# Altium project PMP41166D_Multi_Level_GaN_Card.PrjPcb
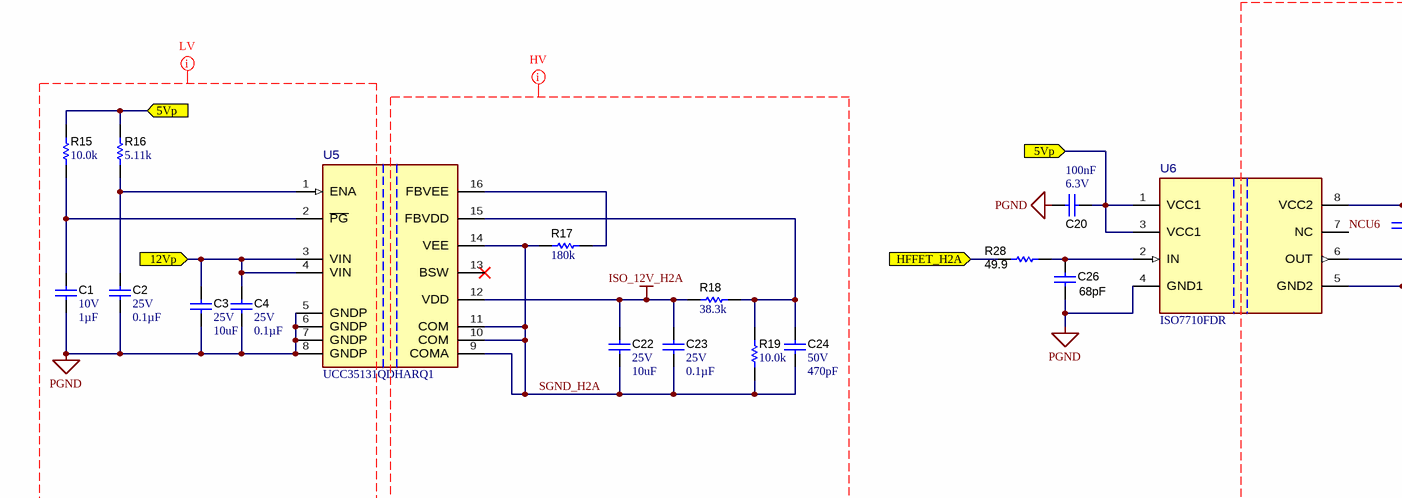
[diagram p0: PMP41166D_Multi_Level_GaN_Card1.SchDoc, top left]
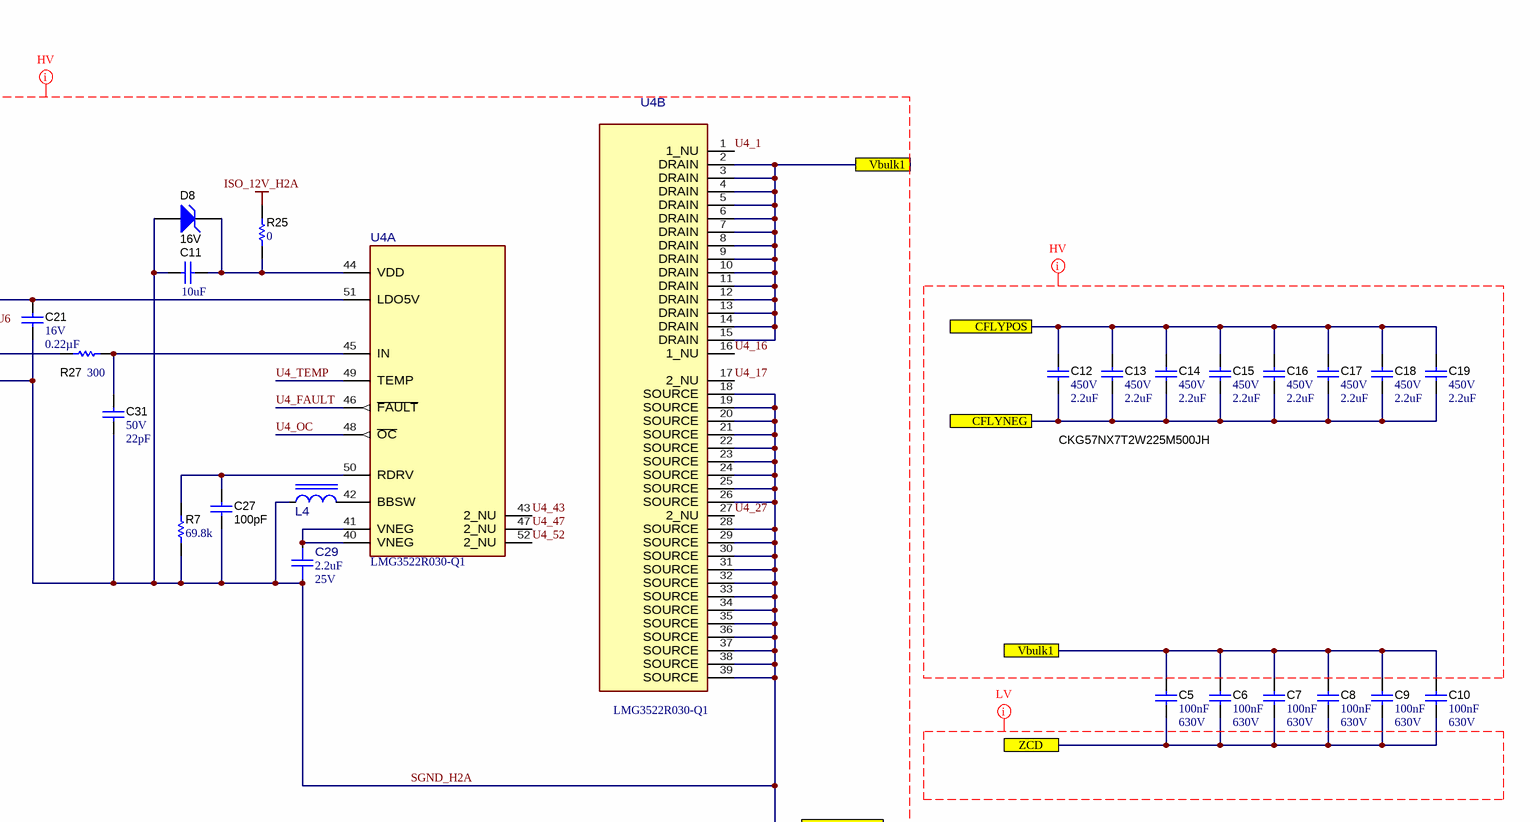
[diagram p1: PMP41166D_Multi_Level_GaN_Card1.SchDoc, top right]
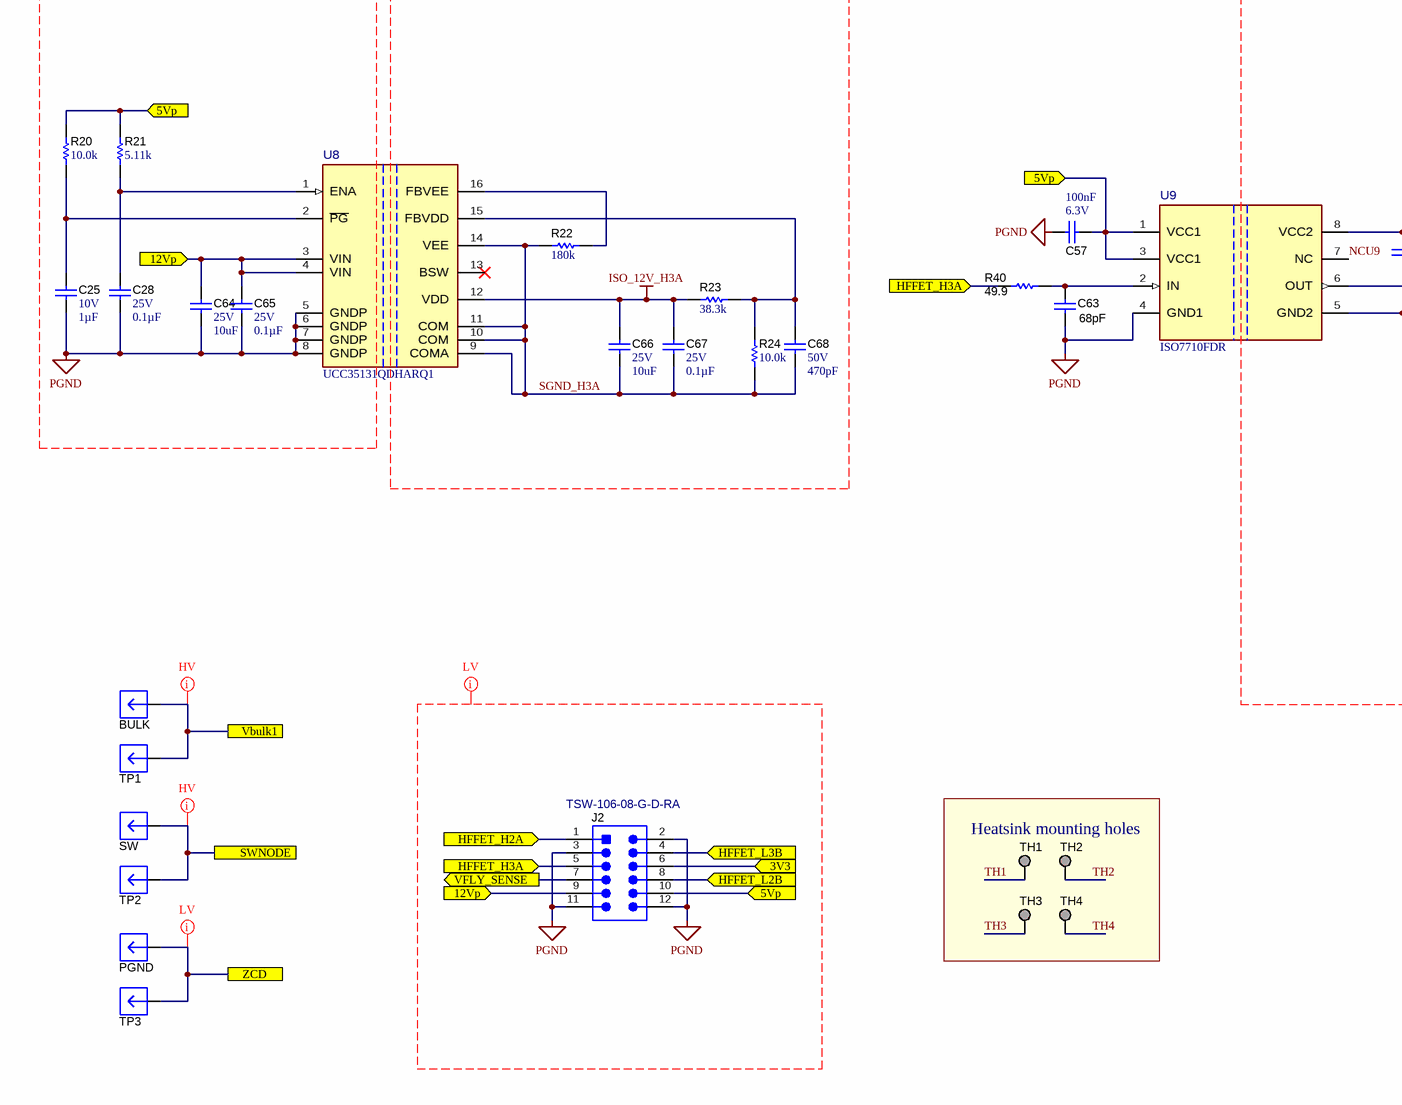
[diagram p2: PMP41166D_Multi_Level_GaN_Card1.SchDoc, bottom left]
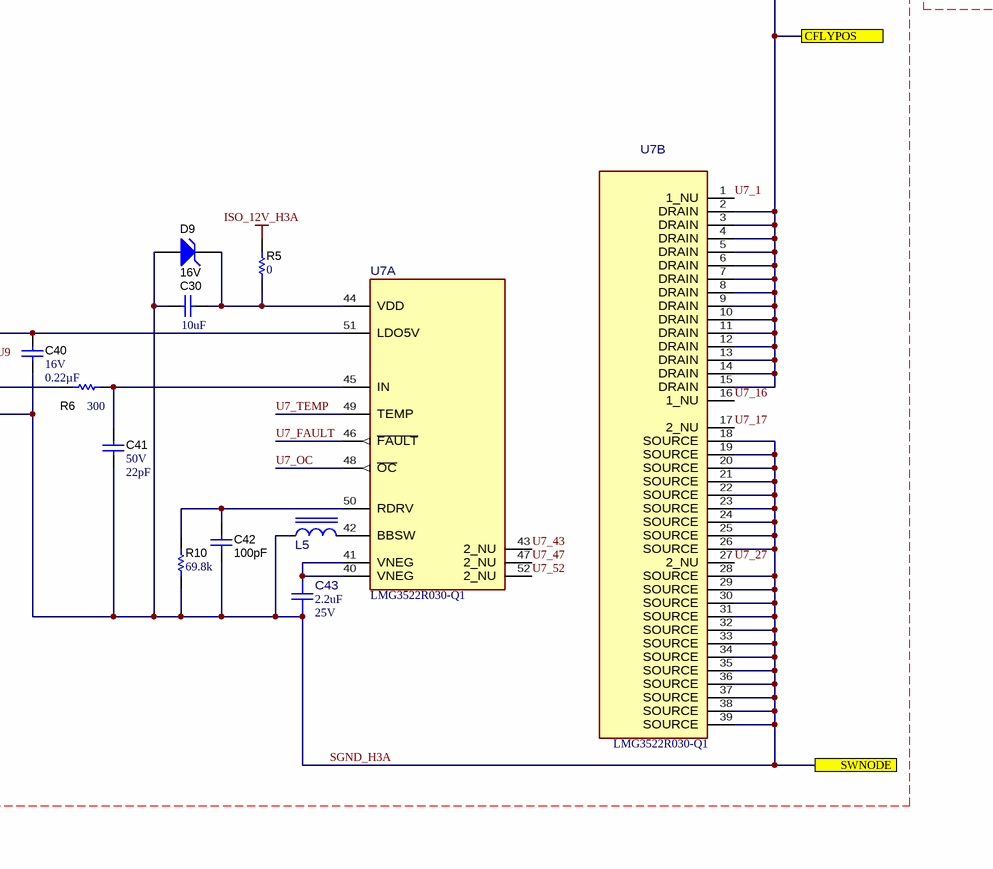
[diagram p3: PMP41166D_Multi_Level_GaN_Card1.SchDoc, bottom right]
CopyrightYear: 2025; PCB_Layout: B. Sun / E. Chen; PCB_Rev: D; PRJ_Customer: Public Release; PRJ_Engineer: B. Sun / E. Chen; PRJ_Number: PMP41166_GaN; PRJ_Title: PMP41166 GaN Card; SCH_Rev: D; TechSupport: http://www.ti.com/support; TID: N/A
3 sheets, 178 parts. Net scope: flat (ports and power ports of the same name join across sheets).
Board file: PMP41166D_Multi_Level_GaN_Card.PcbDoc
Sheets:
  PMP41166D_Multi_Level_GaN_Card1.SchDoc
  PMP41166D_Multi_Level_GaN_Card2.SchDoc
  PMP41166D_Multi_Level_GaN_Card_Hardware.SchDoc

## Sheet PMP41166D_Multi_Level_GaN_Card1.SchDoc
size A2; Date: Not shown in title block; ApprovedBy: Not shown in title block; CheckedBy: Not shown in title block; Author: Not shown in title block; CompanyName: Not shown in title block; Engineer: Not shown in title block; Organization: Not shown in title block; Address1: Not shown in title block; Address2: Not shown in title block; Address3: Not shown in title block; Address4: Not shown in title block; DocumentNumber: 1; Revision: Use project parameter SCH_Rev; SheetNumber: 1; SheetTotal: 3; PageSetup: Record=PageOptions¦CenterHorizontal=True¦CenterVertical=True¦PrintScale=0.69¦XCorrection=1.00¦YCorrection=1.00¦PrintKind=0¦BorderSize=5000000¦LeftOffset=0¦BottomOffset=0¦Orientation=2¦PaperLength=1000¦PaperWidth=1000¦Scale=100¦PaperSource=15¦PrintQuality=600¦MediaType=1¦DitherType=10¦PaperKind=Letter¦PrintScaleMode=1

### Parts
BULK  3621-0-32-15-00-00-08-0  [Mill-Max_3621-0-32-xx-00-00-08-0]  (value not drawn)
C1  VDC_V: 10V  ValueDisplayed: 1µF  [0402]  (hidden comment: CC0402MRX5R6BB105)
C2  VDC_V: 25V  ValueDisplayed: 0.1µF  [0402]  (hidden comment: CGA2B3X7R1E104K050BB)
C3  VDC_V: 25V  ValueDisplayed: 10uF  [0603]  (hidden comment: C1608X5R1E106M080AC)
C4  VDC_V: 25V  ValueDisplayed: 0.1µF  [0402]  (hidden comment: CGA2B3X7R1E104K050BB)
C5  Cap_F: 100nF  VDC_V: 630V  [1210]  (hidden comment: C3225X7T2J104K160AC)
C6  Cap_F: 100nF  VDC_V: 630V  [1210]  (hidden comment: C3225X7T2J104K160AC)
C7  Cap_F: 100nF  VDC_V: 630V  [1210]  (hidden comment: C3225X7T2J104K160AC)
C8  Cap_F: 100nF  VDC_V: 630V  [1210]  (hidden comment: C3225X7T2J104K160AC)
C9  Cap_F: 100nF  VDC_V: 630V  [1210]  (hidden comment: C3225X7T2J104K160AC)
C10  Cap_F: 100nF  VDC_V: 630V  [1210]  (hidden comment: C3225X7T2J104K160AC)
C11  ValueDisplayed: 10uF  [0603]  (hidden comment: GRM188R61E106MA73D)
C12  CKG57NX7T2W225M500JH  VDC_V: 450V  ValueDisplayed: 2.2uF  [CKG57N]
C13  VDC_V: 450V  ValueDisplayed: 2.2uF  [CKG57N]  (hidden comment: CKG57NX7T2W225M500JH)
C14  VDC_V: 450V  ValueDisplayed: 2.2uF  [CKG57N]  (hidden comment: CKG57NX7T2W225M500JH)
C15  VDC_V: 450V  ValueDisplayed: 2.2uF  [CKG57N]  (hidden comment: CKG57NX7T2W225M500JH)
C16  VDC_V: 450V  ValueDisplayed: 2.2uF  [CKG57N]  (hidden comment: CKG57NX7T2W225M500JH)
C17  VDC_V: 450V  ValueDisplayed: 2.2uF  [CKG57N]  (hidden comment: CKG57NX7T2W225M500JH)
C18  VDC_V: 450V  ValueDisplayed: 2.2uF  [CKG57N]  (hidden comment: CKG57NX7T2W225M500JH)
C19  VDC_V: 450V  ValueDisplayed: 2.2uF  [CKG57N]  (hidden comment: CKG57NX7T2W225M500JH)
C20  Cap_F: 100nF  VDC_V: 6.3V  [0603]  (hidden comment: GRM188R70J104KA01D)
C21  VDC_V: 16V  ValueDisplayed: 0.22µF  [0402]  (hidden comment: GCM155R71C224KE02D)
C22  VDC_V: 25V  ValueDisplayed: 10uF  [0603]  (hidden comment: C1608X5R1E106M080AC)
C23  VDC_V: 25V  ValueDisplayed: 0.1µF  [0402]  (hidden comment: CGA2B3X7R1E104K050BB)
C24  VDC_V: 50V  ValueDisplayed: 470pF  [0402]  (hidden comment: GRM155R71H471KA01D)
C25  VDC_V: 10V  ValueDisplayed: 1µF  [0402]  (hidden comment: CC0402MRX5R6BB105)
C26  ValueDisplayed: 68pF  [0402]  (hidden comment: C1005C0G1H680J050BA)
C27  ValueDisplayed: 100pF  [0402]  (hidden comment: CGA2B2C0G1H101J050BA)
C28  VDC_V: 25V  ValueDisplayed: 0.1µF  [0402]  (hidden comment: CGA2B3X7R1E104K050BB)
C29  ValueDisplayed: 2.2uF  VDC_V: 25V  [FP-GRM155R61E225KE11D_0402 (1005 metric)-MFG]  (hidden comment: GRM155R61E225KE11D)
C30  ValueDisplayed: 10uF  [0603]  (hidden comment: GRM188R61E106MA73D)
C31  VDC_V: 50V  ValueDisplayed: 22pF  [0402]  (hidden comment: GRM1555C1H220JA01D)
C40  VDC_V: 16V  ValueDisplayed: 0.22µF  [0402]  (hidden comment: GCM155R71C224KE02D)
C41  VDC_V: 50V  ValueDisplayed: 22pF  [0402]  (hidden comment: GRM1555C1H220JA01D)
C42  ValueDisplayed: 100pF  [0402]  (hidden comment: CGA2B2C0G1H101J050BA)
C43  ValueDisplayed: 2.2uF  VDC_V: 25V  [FP-GRM155R61E225KE11D_0402 (1005 metric)-MFG]  (hidden comment: GRM155R61E225KE11D)
C57  Cap_F: 100nF  VDC_V: 6.3V  [0603]  (hidden comment: GRM188R70J104KA01D)
C63  ValueDisplayed: 68pF  [0402]  (hidden comment: C1005C0G1H680J050BA)
C64  VDC_V: 25V  ValueDisplayed: 10uF  [0603]  (hidden comment: C1608X5R1E106M080AC)
C65  VDC_V: 25V  ValueDisplayed: 0.1µF  [0402]  (hidden comment: CGA2B3X7R1E104K050BB)
C66  VDC_V: 25V  ValueDisplayed: 10uF  [0603]  (hidden comment: C1608X5R1E106M080AC)
C67  VDC_V: 25V  ValueDisplayed: 0.1µF  [0402]  (hidden comment: CGA2B3X7R1E104K050BB)
C68  VDC_V: 50V  ValueDisplayed: 470pF  [0402]  (hidden comment: GRM155R71H471KA01D)
D8  value 16V  [SOD-123]  (hidden comment: BZT52C16-7-F)
D9  value 16V  [SOD-123]  (hidden comment: BZT52C16-7-F)
J2  TSW-106-08-G-D-RA  [AB12-DEST]
L4  MPIA2510V2-4R7-R  [FP-MPIA2510V2-4R7-R_1008-MFG]  (value not drawn)
L5  MPIA2510V2-4R7-R  [FP-MPIA2510V2-4R7-R_1008-MFG]  (value not drawn)
PGND  3621-0-32-15-00-00-08-0  [Mill-Max_3621-0-32-xx-00-00-08-0]  (value not drawn)
R5  ValueDisplayed: 0  [0603]  (hidden comment: MCR03EZPJ000)
R6  ValueDisplayed: 300  [0402]  (hidden comment: CRCW0402300RJNED)
R7  ValueDisplayed: 69.8k  [0402]  (hidden comment: MCR01MZPF6982)
R10  ValueDisplayed: 69.8k  [0402]  (hidden comment: MCR01MZPF6982)
R15  ValueDisplayed: 10.0k  [0402]  (hidden comment: RT0402BRD0710KL)
R16  ValueDisplayed: 5.11k  [0402]  (hidden comment: CRCW04025K11FKED)
R17  ValueDisplayed: 180k  [0402]  (hidden comment: RC0402FR-07180KL)
R18  ValueDisplayed: 38.3k  [0402]  (hidden comment: CRCW040238K3FKED)
R19  ValueDisplayed: 10.0k  [0402]  (hidden comment: RT0402BRD0710KL)
R20  ValueDisplayed: 10.0k  [0402]  (hidden comment: RT0402BRD0710KL)
R21  ValueDisplayed: 5.11k  [0402]  (hidden comment: CRCW04025K11FKED)
R22  ValueDisplayed: 180k  [0402]  (hidden comment: RC0402FR-07180KL)
R23  ValueDisplayed: 38.3k  [0402]  (hidden comment: CRCW040238K3FKED)
R24  ValueDisplayed: 10.0k  [0402]  (hidden comment: RT0402BRD0710KL)
R25  ValueDisplayed: 0  [0603]  (hidden comment: MCR03EZPJ000)
R27  ValueDisplayed: 300  [0402]  (hidden comment: CRCW0402300RJNED)
R28  ValueDisplayed: 49.9  [0402]  (hidden comment: CRCW040249R9FKED)
R40  ValueDisplayed: 49.9  [0402]  (hidden comment: CRCW040249R9FKED)
SW  3621-0-32-15-00-00-08-0  [Mill-Max_3621-0-32-xx-00-00-08-0]  (value not drawn)
TH1  (no value)  [TP_H045P075]  (no BOM)
TH2  (no value)  [TP_H045P075]  (no BOM)
TH3  (no value)  [TP_H045P075]  (no BOM)
TH4  (no value)  [TP_H045P075]  (no BOM)
TP1  3621-0-32-15-00-00-08-0  [Mill-Max_3621-0-32-xx-00-00-08-0]  (value not drawn)
TP2  3621-0-32-15-00-00-08-0  [Mill-Max_3621-0-32-xx-00-00-08-0]  (value not drawn)
TP3  3621-0-32-15-00-00-08-0  [Mill-Max_3621-0-32-xx-00-00-08-0]  (value not drawn)
U4  LMG3522R030-Q1  [RQS0052C-C01-MFG]  (parts A,B of 2)
U5  UCC35131QDHARQ1  [DHA0016A-MFG]
U6  ISO7710FDR  [D0008B-MFG]
U7  LMG3522R030-Q1  [RQS0052C-C01-MFG]  (parts A,B of 2)
U8  UCC35131QDHARQ1  [DHA0016A-MFG]
U9  ISO7710FDR  [D0008B-MFG]

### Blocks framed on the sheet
Heatsink mounting holes: TH1-TH4

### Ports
3V3 (in), 5Vp (in), 12Vp (in), CFLYNEG, CFLYPOS, HFFET_H2A (in), HFFET_H3A (in), HFFET_L2B (in), HFFET_L3B (in), SWNODE, Vbulk1, VFLY_SENSE (out), ZCD

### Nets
ISO_12V_H2A: C22.1 C23.1 R18.1 R25.1 U5.12(VDD)
ISO_12V_H3A: C66.1 C67.1 R5.1 R23.1 U8.12(VDD)
PGND: C1.2 C2.2 C3.2 C4.2 C20.2 C25.2 C26.2 C28.2 C57.2 C63.2 C64.2 C65.2 J2.2 J2.3 J2.11 J2.12 U5.5(GNDP) U5.6(GNDP) U5.7(GNDP) U5.8(GNDP) U6.4(GND1) U8.5(GNDP) U8.6(GNDP) U8.7(GNDP) U8.8(GNDP) U9.4(GND1)
3V3: J2.6 ; port 3V3
5Vp: C20.1 C57.1 J2.10 R15.2 R16.2 R20.2 R21.2 U6.1(VCC1) U6.3(VCC1) U9.1(VCC1) U9.3(VCC1) ; port 5Vp
12Vp: C3.1 C4.1 C64.1 C65.1 J2.9 U5.3(VIN) U5.4(VIN) U8.3(VIN) U8.4(VIN) ; port 12Vp
HFFET_H2A: J2.1 R28.1 ; port HFFET_H2A
HFFET_H3A: J2.5 R40.1 ; port HFFET_H3A
HFFET_L2B: J2.8 ; port HFFET_L2B
HFFET_L3B: J2.4 ; port HFFET_L3B
NCU6: U6.7(NC)
NCU9: U9.7(NC)
SGND_H2A: C11.2 C12.1 C13.1 C14.1 C15.1 C16.1 C17.1 C18.1 C19.1 C21.2 C22.2 C23.2 C24.2 C27.2 C29.1 C31.2 D8.2(A) L4.1 R7.1 R17.1 R19.1 U4.18(SOURCE) U4.19(SOURCE) U4.20(SOURCE) U4.21(SOURCE) U4.22(SOURCE) U4.23(SOURCE) U4.24(SOURCE) U4.25(SOURCE) U4.26(SOURCE) U4.28(SOURCE) U4.29(SOURCE) U4.30(SOURCE) U4.31(SOURCE) U4.32(SOURCE) U4.33(SOURCE) U4.34(SOURCE) U4.35(SOURCE) U4.36(SOURCE) U4.37(SOURCE) U4.38(SOURCE) U4.39(SOURCE) U5.9(COMA) U5.10(COM) U5.11(COM) U5.14(VEE) U6.5(GND2) U7.2(DRAIN) U7.3(DRAIN) U7.4(DRAIN) U7.5(DRAIN) U7.6(DRAIN) U7.7(DRAIN) U7.8(DRAIN) U7.9(DRAIN) U7.10(DRAIN) U7.11(DRAIN) U7.12(DRAIN) U7.13(DRAIN) U7.14(DRAIN) U7.15(DRAIN) ; port CFLYPOS
SGND_H3A: C30.2 C40.2 C41.2 C42.2 C43.1 C66.2 C67.2 C68.2 D9.2(A) L5.1 R10.1 R22.1 R24.1 SW.1 TP2.1 U7.18(SOURCE) U7.19(SOURCE) U7.20(SOURCE) U7.21(SOURCE) U7.22(SOURCE) U7.23(SOURCE) U7.24(SOURCE) U7.25(SOURCE) U7.26(SOURCE) U7.28(SOURCE) U7.29(SOURCE) U7.30(SOURCE) U7.31(SOURCE) U7.32(SOURCE) U7.33(SOURCE) U7.34(SOURCE) U7.35(SOURCE) U7.36(SOURCE) U7.37(SOURCE) U7.38(SOURCE) U7.39(SOURCE) U8.9(COMA) U8.10(COM) U8.11(COM) U8.14(VEE) U9.5(GND2) ; port SWNODE
SGND_L2B: C5.1 C6.1 C7.1 C8.1 C9.1 C10.1 PGND.1 TP3.1 ; port ZCD
SGND_L3B: C12.2 C13.2 C14.2 C15.2 C16.2 C17.2 C18.2 C19.2 ; port CFLYNEG
TH1: TH1.1
TH2: TH2.1
TH3: TH3.1
TH4: TH4.1
U4_1: U4.1(1_NU)
U4_16: U4.16(1_NU)
U4_17: U4.17(2_NU)
U4_27: U4.27(2_NU)
U4_43: U4.43(2_NU)
U4_47: U4.47(2_NU)
U4_52: U4.52(2_NU)
U4_FAULT: U4.46(~{FAULT})
U4_OC: U4.48(~{OC})
U4_TEMP: U4.49(TEMP)
U7_1: U7.1(1_NU)
U7_16: U7.16(1_NU)
U7_17: U7.17(2_NU)
U7_27: U7.27(2_NU)
U7_43: U7.43(2_NU)
U7_47: U7.47(2_NU)
U7_52: U7.52(2_NU)
U7_FAULT: U7.46(~{FAULT})
U7_OC: U7.48(~{OC})
U7_TEMP: U7.49(TEMP)
Vbulk1: BULK.1 C5.2 C6.2 C7.2 C8.2 C9.2 C10.2 TP1.1 U4.2(DRAIN) U4.3(DRAIN) U4.4(DRAIN) U4.5(DRAIN) U4.6(DRAIN) U4.7(DRAIN) U4.8(DRAIN) U4.9(DRAIN) U4.10(DRAIN) U4.11(DRAIN) U4.12(DRAIN) U4.13(DRAIN) U4.14(DRAIN) U4.15(DRAIN) ; port Vbulk1
VFLY_SENSE: J2.7 ; port VFLY_SENSE
NetC1_1: C1.1 R15.1 U5.2(~{PG})
NetC2_1: C2.1 R16.1 U5.1(ENA)
NetC11_1: C11.1 D8.1(K) R25.2 U4.44(VDD)
NetC21_1: C21.1 U4.51(LDO5V) U6.8(VCC2)
NetC24_1: C24.1 R18.2 R19.2 U5.15(FBVDD)
NetC25_1: C25.1 R20.1 U8.2(~{PG})
NetC26_1: C26.1 R28.2 U6.2(IN)
NetC27_1: C27.1 R7.2 U4.50(RDRV)
NetC28_1: C28.1 R21.1 U8.1(ENA)
NetC29_2: C29.2 U4.40(VNEG) U4.41(VNEG)
NetC30_1: C30.1 D9.1(K) R5.2 U7.44(VDD)
NetC31_1: C31.1 R27.2 U4.45(IN)
NetC40_1: C40.1 U7.51(LDO5V) U9.8(VCC2)
NetC41_1: C41.1 R6.2 U7.45(IN)
NetC42_1: C42.1 R10.2 U7.50(RDRV)
NetC43_2: C43.2 U7.40(VNEG) U7.41(VNEG)
NetC63_1: C63.1 R40.2 U9.2(IN)
NetC68_1: C68.1 R23.2 R24.2 U8.15(FBVDD)
NetL4_2: L4.2 U4.42(BBSW)
NetL5_2: L5.2 U7.42(BBSW)
NetR6_1: R6.1 U9.6(OUT)
NetR17_2: R17.2 U5.16(FBVEE)
NetR22_2: R22.2 U8.16(FBVEE)
NetR27_1: R27.1 U6.6(OUT)

Not connected (* = marked no-connect by the designer): U5 13(BSW)*; U8 13(BSW)*

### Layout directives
net class HV: (no net found under the mark), ISO_12V_H2A, ISO_12V_H3A, NCU6, NCU9, SGND_H2A, SGND_H3A, U4_1, U4_16, U4_17, U4_27, U4_43, U4_47, U4_52, U4_FAULT, U4_OC, U4_TEMP, U7_1, U7_16, U7_17, U7_27, U7_43, U7_47, U7_52, U7_FAULT, U7_OC, U7_TEMP, Vbulk1
net class LV: (no net found under the mark), PGND, SGND_L2B

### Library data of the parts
BULK PGND SW TP1-TP3 = CMP-0082316-1: Manufacturer: Mill-Max; CompType: PCB Pin; ContactFinish: Gold; Gender: Male; Row_Count: 1
C1 C25 = CMP-0081457-1: CAP, CERM, 1 µF, 10 V,+/- 20%, X5R, 0402; Manufacturer: Yageo America; TaMin_C: -55°C; Polarized: N; SizeAreaWB_mm2: 3; U/M: EA; Value: 1uF; TaMax_C: 85°C; SizeZ_mm: 0.6; SizeX_mm: 1; SizeY_mm: 0.5; AEC Category: Q200
C2 C4 C23 C28 C65 C67 = CMP-0080610-1: CAP, CERM, 0.1 µF, 25 V,+/- 10%, X7R, AEC-Q200 Grade 1, 0402; Manufacturer: TDK; TaMin_C: -55°C; Polarized: N; SizeAreaWB_mm2: 3; U/M: EA; Value: 0.1uF; TaMax_C: 125°C; SizeZ_mm: 0.6; SizeX_mm: 1; SizeY_mm: 0.5; AEC Qualified: Y; Cap_F: 100nF; AEC Category: Q200
C3 C22 C64 C66 = CMP-0007007-5: CAP, CERM, 10 uF, 25 V, +/- 20%, X5R, 0603; Manufacturer: TDK; TaMin_C: -55°C; ESR_ohm: 4.639m; Polarized: N; SizeAreaWB_mm2: 4.68; Value1: 0.004639 ohm; U/M: EA; Value: 10uF; TaMax_C: 85°C; SizeZ_mm: 1; SizeX_mm: 1.6; SizeY_mm: 0.8; SizeArea_mm2: 1.28; Cap_F: 10µF; IRMS_A: 2.41407A; AEC Category: Q200
C5-C10 = CMP-0009136-2: CAP, CERM, 0.1 uF, 630 V, +/- 10%, X7T, 1210; Manufacturer: TDK; TaMin_C: -55°C; Polarized: N; SizeAreaWB_mm2: 14.7; Value1: Unknown; U/M: EA; Value: 0.1uF; TaMax_C: 125°C; SizeZ_mm: 1.35; SizeX_mm: 3.2; SizeY_mm: 2.5; SizeArea_mm2: 8; AEC Category: Q200
C11 C30 = CMP-0007344-5: CAP, CERM, 10 uF, 25 V, +/- 20%, X5R, 0603; Manufacturer: MuRata; TaMin_C: -55°C; Polarized: N; SizeAreaWB_mm2: 4.68; Value1: Unknown; U/M: EA; Value: 10uF; TaMax_C: 85°C; SizeZ_mm: 1; SizeX_mm: 1.6; SizeY_mm: 0.8; Value2: 25V; SizeArea_mm2: 1.28; Cap_F: 10µF; AEC Category: Q200
C12-C19 = CMP-0009428-1: CAP, CERM, 2.2 uF, 450 V, +/- 20%, X7T, AEC-Q200 Grade 1, 6x5x5mm; Manufacturer: TDK; TaMin_C: -55°C; Polarized: N; SizeAreaWB_mm2: 56; Value1: Unknown; U/M: EA; Value: 2.2uF; TaMax_C: 125°C; SizeZ_mm: 5.5; SizeX_mm: 6; SizeY_mm: 5; Cap_Case: 2220; SizeArea_mm2: 30; AEC Qualified: Y; Cap_F: 2.2µF; AEC Grade: 1; AEC Category: Q200
C20 C57 = CMP-0007359-4: CAP, CERM, 0.1 uF, 6.3 V, +/- 10%, X7R, 0603; Manufacturer: MuRata; TaMin_C: -55°C; Polarized: N; SizeAreaWB_mm2: 4.68; Value1: Unknown; U/M: EA; Value: 0.1uF; TaMax_C: 125°C; SizeZ_mm: 1; SizeX_mm: 1.6; SizeY_mm: 0.8; SizeArea_mm2: 1.28; AEC Category: Q200
C21 C40 = CMP-0078265-1: CAP, CERM, 0.22 µF, 16 V,+/- 10%, X7R, AEC-Q200 Grade 1, 0402; Manufacturer: MuRata; TaMin_C: -55°C; Polarized: N; SizeAreaWB_mm2: 3; U/M: EA; Value: 0.22uF; TaMax_C: 125°C; SizeZ_mm: 0.6; SizeX_mm: 1; SizeY_mm: 0.5; AEC Qualified: Y; Cap_F: 220nF; AEC Category: Q200
C24 C68 = CMP-0006691-2: CAP, CERM, 470 pF, 50 V, +/- 10%, X7R, 0402; Manufacturer: MuRata; TaMin_C: -55°C; Polarized: N; SizeAreaWB_mm2: 3; Value1: Unknown; U/M: EA; Value: 470pF; TaMax_C: 125°C; SizeZ_mm: 0.6; SizeX_mm: 1; SizeY_mm: 0.5; AEC Category: Q200
C26 C63 = CMP-0006251-2: CAP, CERM, 68 pF, 50 V, +/- 5%, C0G/NP0, 0402; Manufacturer: TDK; Alternate Manufacturer: Murata; Alternate PartNumber: GRM1555C1H680JA01D; TaMin_C: -55°C; Polarized: N; SizeAreaWB_mm2: 3; Value1: Unknown; U/M: EA; Value: 68pF; TaMax_C: 125°C; SizeZ_mm: 0.6; SizeX_mm: 1; SizeY_mm: 0.5; Value2: 50V; AEC Category: Q200
C27 C42 = CMP-0006308-1: CAP, CERM, 100 pF, 50 V, +/- 5%, C0G/NP0, AEC-Q200 Grade 1, 0402; Manufacturer: TDK; TaMin_C: -55°C; Polarized: N; SizeAreaWB_mm2: 3; Value1: Unknown; U/M: EA; Value: 100pF; TaMax_C: 125°C; SizeZ_mm: 0.6; SizeX_mm: 1; SizeY_mm: 0.5; Value2: 50V; AEC Qualified: Y; AEC Category: Q200
C29 C43 = CMP-0089929-1: 2.2µF ±10% 25V Ceramic Capacitor X5R 0402 (1005 Metric); Manufacturer: Murata; SizeZ_mm: 0.7mm; AEC Qualified: No; TempCo: 15%
C31 C41 = CMP-0006439-2: CAP, CERM, 22 pF, 50 V, +/- 5%, C0G/NP0, 0402; Manufacturer: MuRata; TaMin_C: -55°C; Polarized: N; SizeAreaWB_mm2: 3; Value1: Unknown; U/M: EA; Value: 22pF; TaMax_C: 125°C; SizeZ_mm: 0.6; SizeX_mm: 1; SizeY_mm: 0.5; AEC Category: Q200
D8 D9 = CMP-0005769-2: Diode, Zener, 16 V, 500 mW, AEC-Q101, SOD-123; Manufacturer: Diodes Inc.; Power_W: 500mW; SizeAreaWB_mm2: 13.095; Value1: 0.5W; RJA_CperW: 338; U/M: EA; SizeZ_mm: 1.35; SizeX_mm: 3.85; SizeY_mm: 1.7; SizeArea_mm2: 6.545; AEC Qualified: Y; AEC Category: Q101
J2 = CMP-0075414-2: Header, 100mil, 6x2, Gold, R/A, TH; Manufacturer: Samtec; Pitch_mm: 2.54; Cert_VDE: N; Gender: Male; Cert_CSA: Y; Current_A: 6.3A; Voltage_V: 550V; Row_Count: 2
L4 L5 = CMP-0090507-1: 4.7µH Shielded Molded Inductor 1.22A 262mOhm Max 1008 (2520 Metric); Manufacturer: Eaton; Material: Metal Composite; Value: 4.7uH; Test Frequency: 1MHz; Isat: 1.8A; DCR_ohm: 0.262; AEC Grade: Grade 1; Tolerance_%: 20%; AEC Qualified: Yes; Self Resonant Frequency: 25MHz; SizeZ_mm: 1.05mm; Shrouded: true
R5 R25 = CMP-0025883-3: RES, 0, 5%, 0.1 W, 0603; Manufacturer: Rohm; Power_W: 100mW; TempCo: 400 ppm/C; Value_Code: 0000; U/M: EA; Value: 0; EIA_Code: E24; SizeX_mm: 1.6; SizeY_mm: 0.8; SizeZ_mm: 1; Value2: 0.1W; SizeArea_mm2: 1.28; AEC Qualified: N; VDC_V: 50V; AEC Category: Q200
R6 R27 = CMP-0026902-3: RES, 300, 5%, 0.063 W, AEC-Q200 Grade 0, 0402; Manufacturer: Vishay-Dale; Power_W: 63mW; TempCo: 200 ppm/C; Value_Code: 300R; Value: 300; EIA_Code: E24; SizeX_mm: 1; SizeY_mm: 0.5; SizeZ_mm: 0.6; Value2: 0.063W; AEC Qualified: Y; VDC_V: 50V; AEC Category: Q200; AEC Grade: 0
R7 R10 = CMP-0026720-1: RES, 69.8 k, 1%, 0.063 W, 0402; Manufacturer: Rohm; Power_W: 63mW; TempCo: 100 ppm/C; Value_Code: 69k8; U/M: EA; Value: 69.8k; EIA_Code: E96; SizeX_mm: 1; SizeY_mm: 0.5; SizeZ_mm: 0.6; Value2: 0.063W; AEC Qualified: N; VDC_V: 50V; AEC Category: Q200
R15 R19 R20 R24 = CMP-0065360-1: RES, 10.0 k, .1%, .0625 W, 0402; Manufacturer: Yageo America; Power_W: 62.5mW; TempCo: 25 ppm/C; Value_Code: 10k0; U/M: EA; Value: 10.0k; EIA_Code: E192; Tolerance_%: 0.1%; Res_ohm: 10k; SizeX_mm: 1.0; SizeY_mm: 0.5; SizeZ_mm: 0.6; Value2: .0625W; VDC_V: 50V; AEC Category: Q200
R16 R21 = CMP-0026463-2: RES, 5.11 k, 1%, 0.063 W, AEC-Q200 Grade 0, 0402; Manufacturer: Vishay-Dale; Power_W: 63mW; TempCo: 100 ppm/C; Value_Code: 5k11; Value: 5.11k; EIA_Code: E96; SizeX_mm: 1; SizeY_mm: 0.5; SizeZ_mm: 0.6; Value2: 0.063W; AEC Qualified: Y; VDC_V: 50V; AEC Category: Q200; AEC Grade: 0
R17 R22 = CMP-0026723-1: RES, 180 k, 1%, 0.063 W, 0402; Manufacturer: Yageo America; Power_W: 63mW; TempCo: 100 ppm/C; U/M: EA; Value: 180k; SizeX_mm: 1; SizeY_mm: 0.5; SizeZ_mm: 0.6; Value2: 0.063W; AEC Qualified: N; VDC_V: 50V; AEC Category: Q200
R18 R23 = CMP-0026323-1: RES, 38.3 k, 1%, 0.063 W, 0402; Manufacturer: Vishay-Dale; Power_W: 63mW; TempCo: 100 ppm/C; Value_Code: 38k3; U/M: EA; Value: 38.3k; EIA_Code: E96; SizeX_mm: 1; SizeY_mm: 0.5; SizeZ_mm: 0.6; Value2: 0.063W; VDC_V: 50V; AEC Category: Q200
R28 R40 = CMP-0026404-2: RES, 49.9, 1%, 0.063 W, AEC-Q200 Grade 0, 0402; Manufacturer: Vishay-Dale; Power_W: 63mW; TempCo: 100 ppm/C; Value_Code: 49R9; Value: 49.9; EIA_Code: E96; SizeX_mm: 1; SizeY_mm: 0.5; SizeZ_mm: 0.6; Value2: 0.063W; AEC Qualified: Y; VDC_V: 50V; AEC Category: Q200; AEC Grade: 0
TH1-TH4 = CMP-0003719-1: Testpoint; Manufacturer: Texas Instruments; Key: TP_H0.45P0.75; CompType: Pad
U4 U7 = CMP-0094892-1: 650-V 30-mΩ GaN FET with Integrated Driver, Protection, and Temperature Reporting; Part Number: LMG3525R030-Q1; Manufacturer: Texas Instruments; Output Voltage: 520V; Nominal Supply Current: 16mA; Min Supply Voltage: 7.5V; Standoff Height: 0mm; AEC Grade: Grade 1; Max Supply Voltage: 18V; Number Of Outputs: 1; AEC Qualified: Yes; TJmax_C: +150°C; SizeZ_mm: 1mm; TaMax_C: +125°C; TaMin_C: -40°C
U5 U8 = CMP-0126653-2: Automotive 2.0W, 12V VIN, High-Density, > 5kVRMS, Isolated DC/DC Module; Manufacturer: Texas Instruments; SizeZ_mm: 2.6mm; AEC Qualified: Yes; AEC Grade: Grade 1; Max Supply Voltage: 20V; Min Supply Voltage: 5.5V; Number Of Outputs: 2; Output Type: AdjustableProgrammable; Output Voltage: -2-8/12-18V; Standoff Height: 0.1mm; TaMax_C: +125°C; TaMin_C: -40°C; TJmax_C: +150°C; AEC Category: Q200; CompType: IC
U6 U9 = CMP-0089765-2: General Purpose Digital Isolator 3000Vrms 1 Channel 100Mbps 85kV/µs CMTI 8-SOIC (0.154", 3.90mm Width); Manufacturer: Texas Instruments; CompType: IC; AEC Category: Q200; TJmax_C: +150°C; Standoff Height: 0.11mm; Interface: CAN; Max Supply Voltage: 5.5V; AEC Qualified: No; Nominal Supply Current: 156-311mA; Min Supply Voltage: 2.25V; TaMax_C: +125°C; SizeZ_mm: 1.75mm; TaMin_C: -55°C

## Sheet PMP41166D_Multi_Level_GaN_Card2.SchDoc
size A2; Date: Not shown in title block; ApprovedBy: Not shown in title block; CheckedBy: Not shown in title block; Author: Not shown in title block; CompanyName: Not shown in title block; Engineer: Not shown in title block; Organization: Not shown in title block; Address1: Not shown in title block; Address2: Not shown in title block; Address3: Not shown in title block; Address4: Not shown in title block; DocumentNumber: 1; Revision: Use project parameter SCH_Rev; SheetNumber: 2; SheetTotal: 3; PageSetup: Record=PageOptions¦CenterHorizontal=True¦CenterVertical=True¦PrintScale=0.69¦XCorrection=1.00¦YCorrection=1.00¦PrintKind=0¦BorderSize=5000000¦LeftOffset=0¦BottomOffset=0¦Orientation=2¦PaperLength=1000¦PaperWidth=1000¦Scale=100¦PaperSource=15¦PrintQuality=600¦MediaType=1¦DitherType=10¦PaperKind=Letter¦PrintScaleMode=1
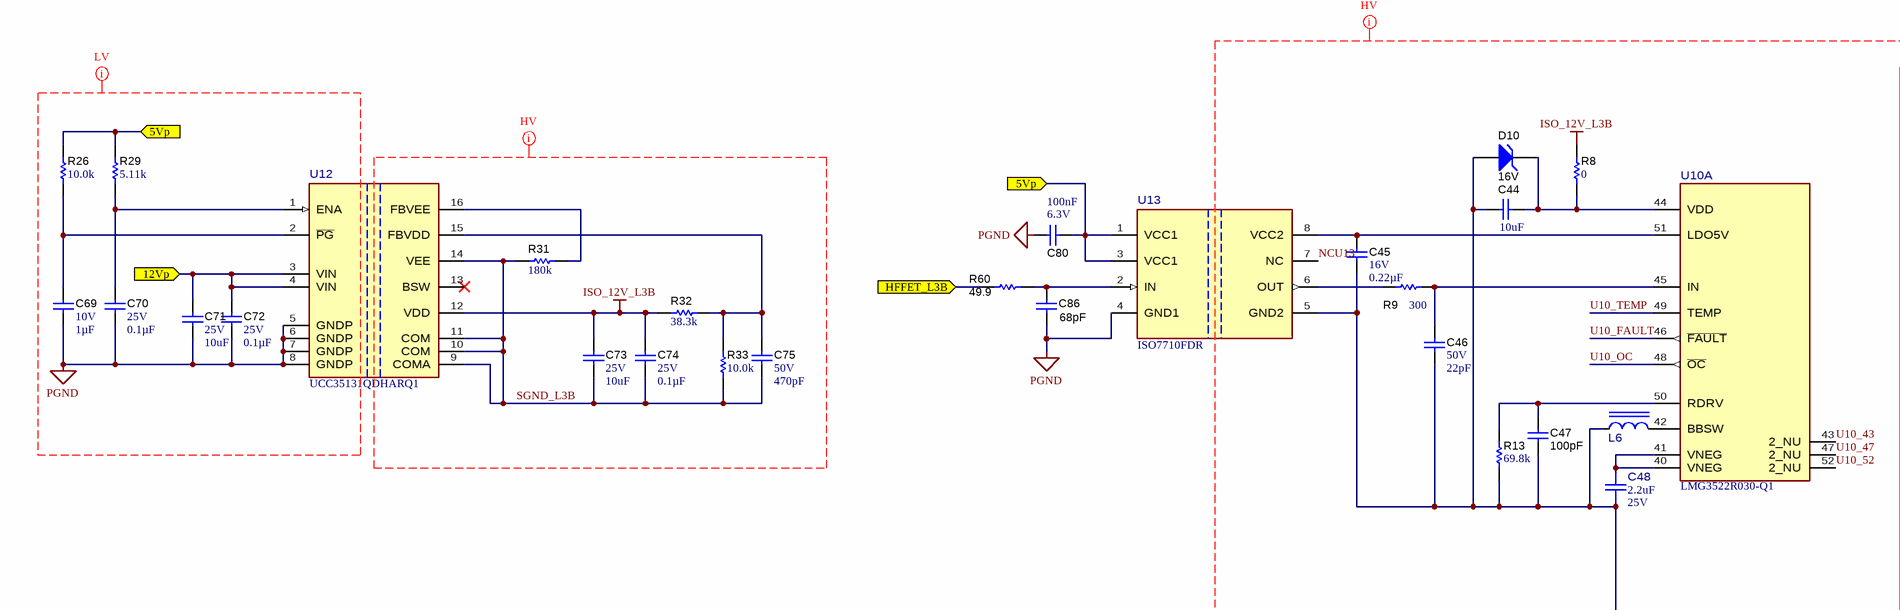
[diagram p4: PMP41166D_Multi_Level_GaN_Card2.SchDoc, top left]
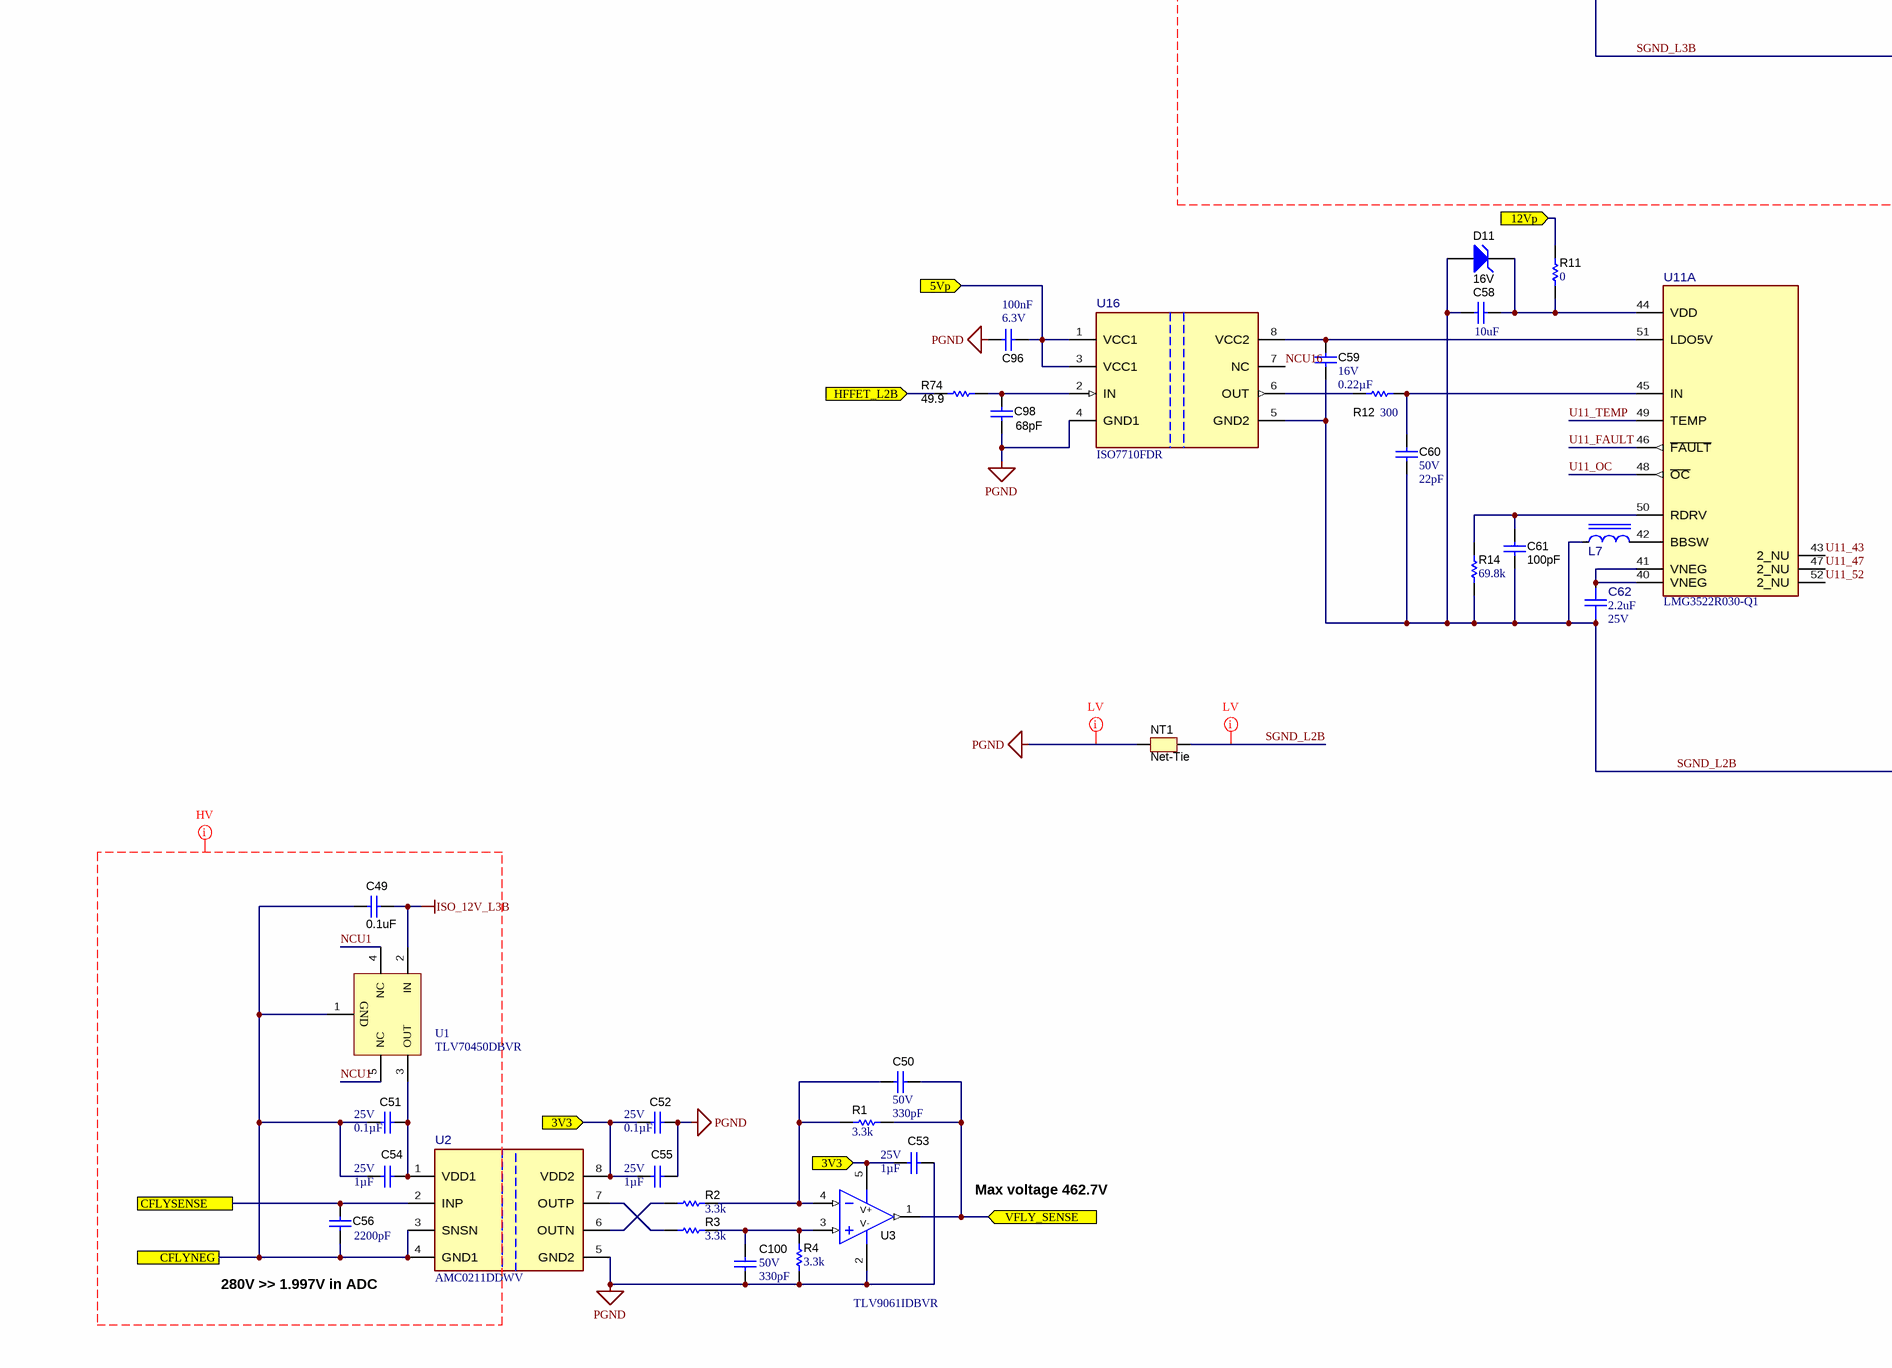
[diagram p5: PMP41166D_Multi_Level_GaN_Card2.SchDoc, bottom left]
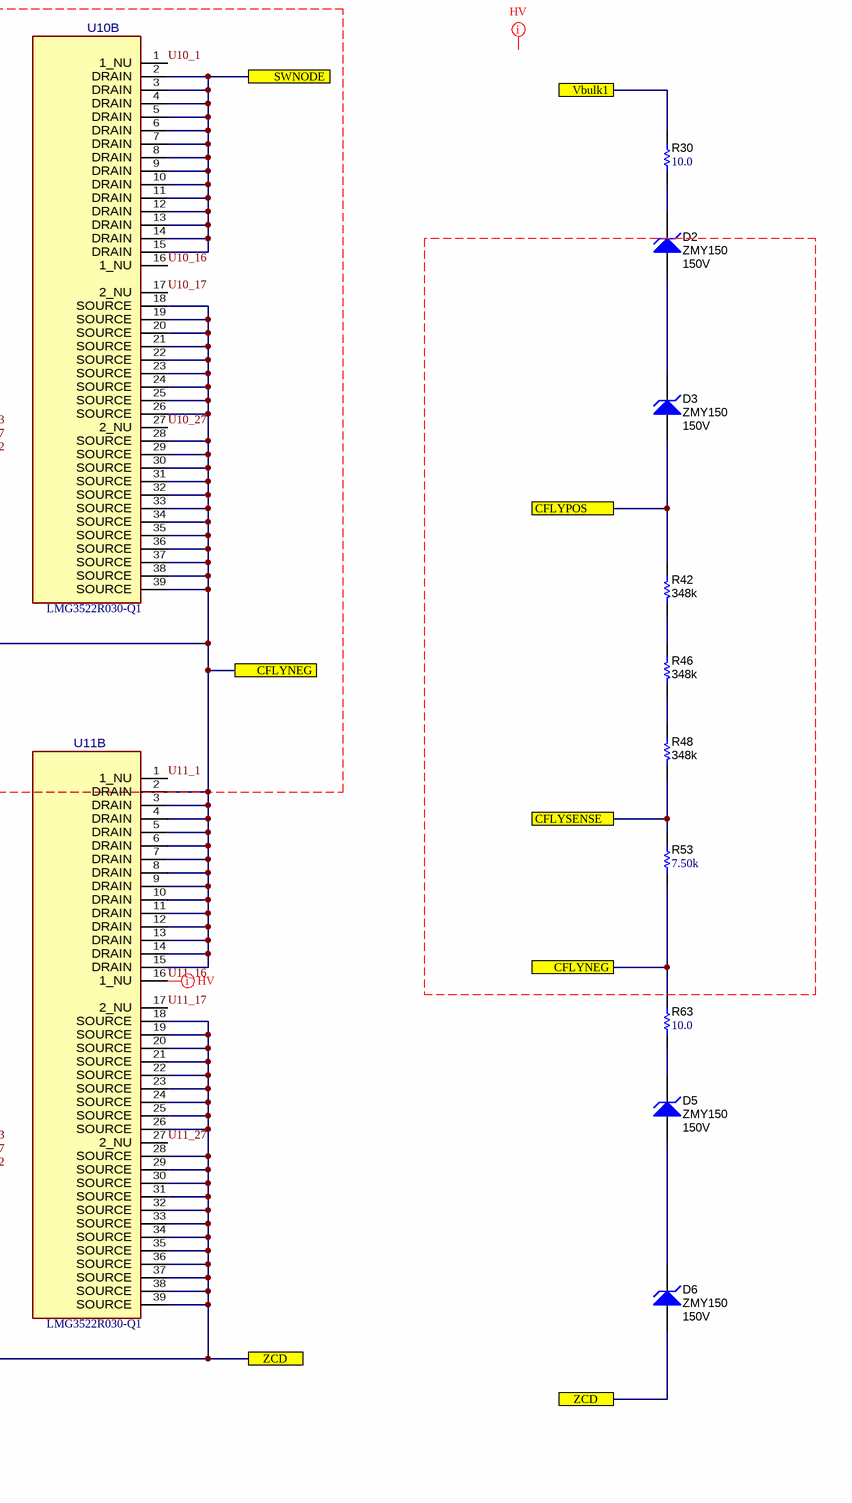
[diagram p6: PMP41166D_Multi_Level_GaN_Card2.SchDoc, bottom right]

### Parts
C44  ValueDisplayed: 10uF  [0603]  (hidden comment: GRM188R61E106MA73D)
C45  VDC_V: 16V  ValueDisplayed: 0.22µF  [0402]  (hidden comment: GCM155R71C224KE02D)
C46  VDC_V: 50V  ValueDisplayed: 22pF  [0402]  (hidden comment: GRM1555C1H220JA01D)
C47  ValueDisplayed: 100pF  [0402]  (hidden comment: CGA2B2C0G1H101J050BA)
C48  ValueDisplayed: 2.2uF  VDC_V: 25V  [FP-GRM155R61E225KE11D_0402 (1005 metric)-MFG]  (hidden comment: GRM155R61E225KE11D)
C49  ValueDisplayed: 0.1uF  [0402]  (hidden comment: C1005X7R1H104K050BB)
C50  VDC_V: 50V  ValueDisplayed: 330pF  [0402]  (hidden comment: GRM1555C1H331FA01J)
C51  VDC_V: 25V  ValueDisplayed: 0.1µF  [0402]  (hidden comment: CGA2B3X7R1E104K050BB)
C52  VDC_V: 25V  ValueDisplayed: 0.1µF  [0402]  (hidden comment: CGA2B3X7R1E104K050BB)
C53  VDC_V: 25V  ValueDisplayed: 1µF  [0402]  (hidden comment: GRM155R61E105MA12D)
C54  VDC_V: 25V  ValueDisplayed: 1µF  [0402]  (hidden comment: GRM155R61E105MA12D)
C55  VDC_V: 25V  ValueDisplayed: 1µF  [0402]  (hidden comment: GRM155R61E105MA12D)
C56  ValueDisplayed: 2200pF  [0402]  (hidden comment: GRM155R71E222KA01D)
C58  ValueDisplayed: 10uF  [0603]  (hidden comment: GRM188R61E106MA73D)
C59  VDC_V: 16V  ValueDisplayed: 0.22µF  [0402]  (hidden comment: GCM155R71C224KE02D)
C60  VDC_V: 50V  ValueDisplayed: 22pF  [0402]  (hidden comment: GRM1555C1H220JA01D)
C61  ValueDisplayed: 100pF  [0402]  (hidden comment: CGA2B2C0G1H101J050BA)
C62  ValueDisplayed: 2.2uF  VDC_V: 25V  [FP-GRM155R61E225KE11D_0402 (1005 metric)-MFG]  (hidden comment: GRM155R61E225KE11D)
C69  VDC_V: 10V  ValueDisplayed: 1µF  [0402]  (hidden comment: CC0402MRX5R6BB105)
C70  VDC_V: 25V  ValueDisplayed: 0.1µF  [0402]  (hidden comment: CGA2B3X7R1E104K050BB)
C71  VDC_V: 25V  ValueDisplayed: 10uF  [0603]  (hidden comment: C1608X5R1E106M080AC)
C72  VDC_V: 25V  ValueDisplayed: 0.1µF  [0402]  (hidden comment: CGA2B3X7R1E104K050BB)
C73  VDC_V: 25V  ValueDisplayed: 10uF  [0603]  (hidden comment: C1608X5R1E106M080AC)
C74  VDC_V: 25V  ValueDisplayed: 0.1µF  [0402]  (hidden comment: CGA2B3X7R1E104K050BB)
C75  VDC_V: 50V  ValueDisplayed: 470pF  [0402]  (hidden comment: GRM155R71H471KA01D)
C80  Cap_F: 100nF  VDC_V: 6.3V  [0603]  (hidden comment: GRM188R70J104KA01D)
C86  ValueDisplayed: 68pF  [0402]  (hidden comment: C1005C0G1H680J050BA)
C96  Cap_F: 100nF  VDC_V: 6.3V  [0603]  (hidden comment: GRM188R70J104KA01D)
C98  ValueDisplayed: 68pF  [0402]  (hidden comment: C1005C0G1H680J050BA)
C100  VDC_V: 50V  ValueDisplayed: 330pF  [0402]  (hidden comment: GRM1555C1H331FA01J)
D2  ZMY150  value 150V  [DO-213AB]
D3  ZMY150  value 150V  [DO-213AB]
D5  ZMY150  value 150V  [DO-213AB]
D6  ZMY150  value 150V  [DO-213AB]
D10  value 16V  [SOD-123]  (hidden comment: BZT52C16-7-F)
D11  value 16V  [SOD-123]  (hidden comment: BZT52C16-7-F)
L6  MPIA2510V2-4R7-R  [FP-MPIA2510V2-4R7-R_1008-MFG]  (value not drawn)
L7  MPIA2510V2-4R7-R  [FP-MPIA2510V2-4R7-R_1008-MFG]  (value not drawn)
NT1  Net-Tie  [Net-Tie_50milWide_30milLong]  (net tie, no BOM)
R1  ValueDisplayed: 3.3k  [0402]  (hidden comment: CRCW04023K30JNED)
R2  ValueDisplayed: 3.3k  [0402]  (hidden comment: CRCW04023K30JNED)
R3  ValueDisplayed: 3.3k  [0402]  (hidden comment: CRCW04023K30JNED)
R4  ValueDisplayed: 3.3k  [0402]  (hidden comment: CRCW04023K30JNED)
R8  ValueDisplayed: 0  [0603]  (hidden comment: MCR03EZPJ000)
R9  ValueDisplayed: 300  [0402]  (hidden comment: CRCW0402300RJNED)
R11  ValueDisplayed: 0  [0603]  (hidden comment: MCR03EZPJ000)
R12  ValueDisplayed: 300  [0402]  (hidden comment: CRCW0402300RJNED)
R13  ValueDisplayed: 69.8k  [0402]  (hidden comment: MCR01MZPF6982)
R14  ValueDisplayed: 69.8k  [0402]  (hidden comment: MCR01MZPF6982)
R26  ValueDisplayed: 10.0k  [0402]  (hidden comment: RT0402BRD0710KL)
R29  ValueDisplayed: 5.11k  [0402]  (hidden comment: CRCW04025K11FKED)
R30  ValueDisplayed: 10.0  [1206]  (hidden comment: PHP01206E10R0BST5)
R31  ValueDisplayed: 180k  [0402]  (hidden comment: RC0402FR-07180KL)
R32  ValueDisplayed: 38.3k  [0402]  (hidden comment: CRCW040238K3FKED)
R33  ValueDisplayed: 10.0k  [0402]  (hidden comment: RT0402BRD0710KL)
R42  ValueDisplayed: 348k  [1206]  (hidden comment: RC1206FR-07348KL)
R46  ValueDisplayed: 348k  [1206]  (hidden comment: RC1206FR-07348KL)
R48  ValueDisplayed: 348k  [1206]  (hidden comment: RC1206FR-07348KL)
R53  ValueDisplayed: 7.50k  [0402]  (hidden comment: CRCW04027K50FKED)
R60  ValueDisplayed: 49.9  [0402]  (hidden comment: CRCW040249R9FKED)
R63  ValueDisplayed: 10.0  [1206]  (hidden comment: PHP01206E10R0BST5)
R74  ValueDisplayed: 49.9  [0402]  (hidden comment: CRCW040249R9FKED)
U1  TLV70450DBVR  [DBV0005A_N]
U2  AMC0211DDWV  [DWV0008A-MFG]
U3  TLV9061IDBVR  [DBV0005A_N]
U10  LMG3522R030-Q1  [RQS0052C-C01-MFG]  (parts A,B of 2)
U11  LMG3522R030-Q1  [RQS0052C-C01-MFG]  (parts A,B of 2)
U12  UCC35131QDHARQ1  [DHA0016A-MFG]
U13  ISO7710FDR  [D0008B-MFG]
U16  ISO7710FDR  [D0008B-MFG]

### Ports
3V3 (in), 5Vp (in), 12Vp (in), CFLYNEG, CFLYPOS, CFLYSENSE, HFFET_L2B (in), HFFET_L3B (in), SWNODE, Vbulk1, VFLY_SENSE (in), ZCD

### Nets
ISO_12V_L3B: C49.1 C73.1 C74.1 R8.1 R32.1 U1.2(IN) U12.12(VDD)
PGND: C52.1 C53.1 C55.1 C69.2 C70.2 C71.2 C72.2 C80.2 C86.2 C96.2 C98.2 C100.2 NT1.1 R4.1 U2.5(GND2) U3.2(V-) U12.5(GNDP) U12.6(GNDP) U12.7(GNDP) U12.8(GNDP) U13.4(GND1) U16.4(GND1)
3V3: C52.2 C53.2 C55.2 U2.8(VDD2) U3.5(V+) ; port 3V3
5Vp: C80.1 C96.1 R26.2 R29.2 U13.1(VCC1) U13.3(VCC1) U16.1(VCC1) U16.3(VCC1) ; port 5Vp
12Vp: C71.1 C72.1 R11.1 U12.3(VIN) U12.4(VIN) ; port 12Vp
CFLYSENSE: C56.1 R48.1 R53.2 U2.2(INP) ; port CFLYSENSE
HFFET_L2B: R74.1 ; port HFFET_L2B
HFFET_L3B: R60.1 ; port HFFET_L3B
NCU1: U1.4(NC)
NCU1': U1.5(NC)
NCU13: U13.7(NC)
NCU16: U16.7(NC)
SGND_H2A: D3.2(A) R42.2 ; port CFLYPOS
SGND_H3A: U10.2(DRAIN) U10.3(DRAIN) U10.4(DRAIN) U10.5(DRAIN) U10.6(DRAIN) U10.7(DRAIN) U10.8(DRAIN) U10.9(DRAIN) U10.10(DRAIN) U10.11(DRAIN) U10.12(DRAIN) U10.13(DRAIN) U10.14(DRAIN) U10.15(DRAIN) ; port SWNODE
SGND_L2B: C58.2 C59.2 C60.2 C61.2 C62.1 D6.2(A) D11.2(A) L7.1 NT1.2 R14.1 U11.18(SOURCE) U11.19(SOURCE) U11.20(SOURCE) U11.21(SOURCE) U11.22(SOURCE) U11.23(SOURCE) U11.24(SOURCE) U11.25(SOURCE) U11.26(SOURCE) U11.28(SOURCE) U11.29(SOURCE) U11.30(SOURCE) U11.31(SOURCE) U11.32(SOURCE) U11.33(SOURCE) U11.34(SOURCE) U11.35(SOURCE) U11.36(SOURCE) U11.37(SOURCE) U11.38(SOURCE) U11.39(SOURCE) U16.5(GND2) ; port ZCD
SGND_L3B: C44.2 C45.2 C46.2 C47.2 C48.1 C49.2 C51.2 C54.2 C56.2 C73.2 C74.2 C75.2 D10.2(A) L6.1 R13.1 R31.1 R33.1 R53.1 R63.2 U1.1(GND) U2.3(SNSN) U2.4(GND1) U10.18(SOURCE) U10.19(SOURCE) U10.20(SOURCE) U10.21(SOURCE) U10.22(SOURCE) U10.23(SOURCE) U10.24(SOURCE) U10.25(SOURCE) U10.26(SOURCE) U10.28(SOURCE) U10.29(SOURCE) U10.30(SOURCE) U10.31(SOURCE) U10.32(SOURCE) U10.33(SOURCE) U10.34(SOURCE) U10.35(SOURCE) U10.36(SOURCE) U10.37(SOURCE) U10.38(SOURCE) U10.39(SOURCE) U11.2(DRAIN) U11.3(DRAIN) U11.4(DRAIN) U11.5(DRAIN) U11.6(DRAIN) U11.7(DRAIN) U11.8(DRAIN) U11.9(DRAIN) U11.10(DRAIN) U11.11(DRAIN) U11.12(DRAIN) U11.13(DRAIN) U11.14(DRAIN) U11.15(DRAIN) U12.9(COMA) U12.10(COM) U12.11(COM) U12.14(VEE) U13.5(GND2) ; port CFLYNEG
U10_1: U10.1(1_NU)
U10_16: U10.16(1_NU)
U10_17: U10.17(2_NU)
U10_27: U10.27(2_NU)
U10_43: U10.43(2_NU)
U10_47: U10.47(2_NU)
U10_52: U10.52(2_NU)
U10_FAULT: U10.46(~{FAULT})
U10_OC: U10.48(~{OC})
U10_TEMP: U10.49(TEMP)
U11_1: U11.1(1_NU)
U11_16: U11.16(1_NU)
U11_17: U11.17(2_NU)
U11_27: U11.27(2_NU)
U11_43: U11.43(2_NU)
U11_47: U11.47(2_NU)
U11_52: U11.52(2_NU)
U11_FAULT: U11.46(~{FAULT})
U11_OC: U11.48(~{OC})
U11_TEMP: U11.49(TEMP)
Vbulk1: R30.2 ; port Vbulk1
VFLY_SENSE: C50.2 R1.1 U3.1(OUT) ; port VFLY_SENSE
NetC44_1: C44.1 D10.1(K) R8.2 U10.44(VDD)
NetC45_1: C45.1 U10.51(LDO5V) U13.8(VCC2)
NetC46_1: C46.1 R9.2 U10.45(IN)
NetC47_1: C47.1 R13.2 U10.50(RDRV)
NetC48_2: C48.2 U10.40(VNEG) U10.41(VNEG)
NetC50_1: C50.1 R1.2 R2.2 U3.4(IN-)
NetC51_1: C51.1 C54.1 U1.3(OUT) U2.1(VDD1)
NetC58_1: C58.1 D11.1(K) R11.2 U11.44(VDD)
NetC59_1: C59.1 U11.51(LDO5V) U16.8(VCC2)
NetC60_1: C60.1 R12.2 U11.45(IN)
NetC61_1: C61.1 R14.2 U11.50(RDRV)
NetC62_2: C62.2 U11.40(VNEG) U11.41(VNEG)
NetC69_1: C69.1 R26.1 U12.2(~{PG})
NetC70_1: C70.1 R29.1 U12.1(ENA)
NetC75_1: C75.1 R32.2 R33.2 U12.15(FBVDD)
NetC86_1: C86.1 R60.2 U13.2(IN)
NetC98_1: C98.1 R74.2 U16.2(IN)
NetC100_1: C100.1 R3.2 R4.2 U3.3(IN+)
NetD2_1: D2.1(K) R30.1
NetD2_2: D2.2(A) D3.1(K)
NetD5_1: D5.1(K) R63.1
NetD5_2: D5.2(A) D6.1(K)
NetL6_2: L6.2 U10.42(BBSW)
NetL7_2: L7.2 U11.42(BBSW)
NetR2_1: R2.1 U2.6(OUTN)
NetR3_1: R3.1 U2.7(OUTP)
NetR9_1: R9.1 U13.6(OUT)
NetR12_1: R12.1 U16.6(OUT)
NetR31_2: R31.2 U12.16(FBVEE)
NetR42_1: R42.1 R46.2
NetR46_1: R46.1 R48.2

Not connected (* = marked no-connect by the designer): U12 13(BSW)*

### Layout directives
net class HV: (no net found under the mark), ISO_12V_L3B, NCU1, NCU1', NCU13, SGND_L3B, U10_1, U10_16, U10_17, U10_27, U10_43, U10_47, U10_52, U10_FAULT, U10_OC, U10_TEMP, U11_1, U11_16
net class LV: PGND, SGND_L2B

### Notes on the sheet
- Max voltage 462.7V
- 280V >> 1.997V in ADC

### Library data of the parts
C44 C58 = CMP-0007344-5: as C11 on sheet PMP41166D_Multi_Level_GaN_Card1
C45 C59 = CMP-0078265-1: as C21 on sheet PMP41166D_Multi_Level_GaN_Card1
C46 C60 = CMP-0006439-2: as C31 on sheet PMP41166D_Multi_Level_GaN_Card1
C47 C61 = CMP-0006308-1: as C27 on sheet PMP41166D_Multi_Level_GaN_Card1
C48 C62 = CMP-0089929-1: as C29 on sheet PMP41166D_Multi_Level_GaN_Card1
C49 = CMP-0006297-2: CAP, CERM, 0.1 uF, 50 V, +/- 10%, X7R, 0402; Manufacturer: TDK; Polarized: N; Value: 0.1uF; U/M: EA; Cap_F: 100nF; ESR_ohm: 0.039064; Value1: 0.039064 ohm; VDC_V: 50V; IRMS_A: 8.14669dA; TaMin_C: -55°C; TaMax_C: 125°C; AEC Category: Q200; SizeArea_mm2: 0.5; SizeAreaWB_mm2: 3; SizeX_mm: 1; SizeZ_mm: 0.6
C50 C100 = CMP-0006455-2: CAP, CERM, 330 pF, 50 V, +/- 1%, C0G/NP0, 0402; Manufacturer: MuRata; TaMin_C: -55°C; Polarized: N; SizeAreaWB_mm2: 3; Value1: Unknown; U/M: EA; Value: 330pF; TaMax_C: 125°C; SizeZ_mm: 0.6; SizeX_mm: 1; SizeY_mm: 0.5; AEC Category: Q200
C51 C52 C70 C72 C74 = CMP-0080610-1: as C2 on sheet PMP41166D_Multi_Level_GaN_Card1
C53-C55 = CMP-0078625-1: CAP, CERM, 1 µF, 25 V,+/- 20%, X5R, 0402; Manufacturer: MuRata; SizeAreaWB_mm2: 3; SizeArea_mm2: 0.5; AEC Qualified: N; AEC Category: Q200; Value: 1uF; TaMax_C: 85°C; SizeZ_mm: 0.6; TaMin_C: -55°C; U/M: EA; SizeX_mm: 1
C56 = CMP-0006663-2: CAP, CERM, 2200 pF, 25 V, +/- 10%, X7R, 0402; Manufacturer: MuRata; TaMin_C: -55°C; Polarized: N; SizeAreaWB_mm2: 3; Value1: Unknown; U/M: EA; Value: 2200pF; TaMax_C: 125°C; SizeZ_mm: 0.6; SizeX_mm: 1; SizeY_mm: 0.5; Value2: 25V; Cap_F: 2.2nF; AEC Category: Q200
C69 = CMP-0081457-1: as C1 on sheet PMP41166D_Multi_Level_GaN_Card1
C71 C73 = CMP-0007007-5: as C3 on sheet PMP41166D_Multi_Level_GaN_Card1
C75 = CMP-0006691-2: as C24 on sheet PMP41166D_Multi_Level_GaN_Card1
C80 C96 = CMP-0007359-4: as C20 on sheet PMP41166D_Multi_Level_GaN_Card1
C86 C98 = CMP-0006251-2: as C26 on sheet PMP41166D_Multi_Level_GaN_Card1
D2 D3 D5 D6 = CMP-0082173-3: Diode, Zener, 150V; PartNumber: ZGL41-150A-E3/96; Manufacturer: Vishay-Semiconductor; AEC Category: Q101; SizeArea_mm2: 12.573; SizeX_mm: 4.95; SizeAreaWB_mm2: 21.063; Value1: 1W; SizeY_mm: 2.54; AEC Qualified: N; SizeZ_mm: 2.67
D10 D11 = CMP-0005769-2: as D8 on sheet PMP41166D_Multi_Level_GaN_Card1
L6 L7 = CMP-0090507-1: as L4 on sheet PMP41166D_Multi_Level_GaN_Card1
NT1 = CMP-0078142-4: Single point connection between nets.
R1-R4 = CMP-0026918-5: RES, 3.3 k, 5%, 0.063 W, AEC-Q200 Grade 0, 0402; Manufacturer: Vishay-Dale; Power_W: 63mW; TempCo: 200 ppm/C; Value_Code: 3k30; Value: 3.3k; EIA_Code: E24; SizeX_mm: 1; SizeY_mm: 0.5; SizeZ_mm: 0.6; Value2: 0.063W; AEC Qualified: Y; VDC_V: 50V; AEC Category: Q200; AEC Grade: 0
R8 R11 = CMP-0025883-3: as R5 on sheet PMP41166D_Multi_Level_GaN_Card1
R9 R12 = CMP-0026902-3: as R6 on sheet PMP41166D_Multi_Level_GaN_Card1
R13 R14 = CMP-0026720-1: as R7 on sheet PMP41166D_Multi_Level_GaN_Card1
R26 R33 = CMP-0065360-1: as R15 on sheet PMP41166D_Multi_Level_GaN_Card1
R29 = CMP-0026463-2: as R16 on sheet PMP41166D_Multi_Level_GaN_Card1
R30 R63 = CMP-0018790-2: RES, 10.0, 0.1%, 1 W, 1206; Manufacturer: Vishay-Dale; Power_W: 1W; TempCo: 25 ppm/C; Value_Code: 10R0; U/M: EA; Value: 10.0; EIA_Code: E192; Res_ohm: 10; SizeX_mm: 3.2; SizeY_mm: 1.6; SizeZ_mm: 1.35; SizeArea_mm2: 5.12; VDC_V: 100V; AEC Category: Q200
R31 = CMP-0026723-1: as R17 on sheet PMP41166D_Multi_Level_GaN_Card1
R32 = CMP-0026323-1: as R18 on sheet PMP41166D_Multi_Level_GaN_Card1
R42 R46 R48 = CMP-0018215-2: RES, 348 k, 1%, 0.25 W, 1206; Manufacturer: Yageo America; Power_W: 250mW; TempCo: 100 ppm/C; U/M: EA; Value: 348k; EIA_Code: E96; SizeX_mm: 3.2; SizeY_mm: 1.6; SizeZ_mm: 1.35; Value2: 0.25W; SizeArea_mm2: 5.12; VDC_V: 200V; AEC Category: Q200
R53 = CMP-0026555-2: RES, 7.50 k, 1%, 0.063 W, AEC-Q200 Grade 0, 0402; Manufacturer: Vishay-Dale; Power_W: 63mW; TempCo: 100 ppm/C; Value_Code: 7k50; Value: 7.50k; EIA_Code: E96; Res_ohm: 7.5k; SizeX_mm: 1; SizeY_mm: 0.5; SizeZ_mm: 0.6; Value2: 0.063W; AEC Qualified: Y; VDC_V: 50V; AEC Category: Q200; AEC Grade: 0
R60 R74 = CMP-0026404-2: as R28 on sheet PMP41166D_Multi_Level_GaN_Card1
U1 = CMP-0035558-1: Single Output LDO, 150 mA, Fixed 5 V Output, 2.5 to 24 V Input, with Ultra-Low IQ, 5-pin SOT-23 (DBV), -40 to 125 degC, Green (RoHS & no Sb/Br); Manufacturer: Texas Instruments; Vout Adj(Max)(V): 5; Vin(Min)(V): 2.5; Vin(Max)(V): 24; Accuracy(%): 2; SubFamily: Single Channel LDO; Iout(Max)(A): 0.15; Vdo(Typ)(mV): 400; Iq(Typ)(mA): 0.003
U2 = CMP-0124041-1: Precision, 2V Input, Basic and Reinforced Isolated Amplifiers With Fixed-Gain Differential Output; Manufacturer: Texas Instruments; SizeZ_mm: 2.8mm; AEC Qualified: No; Bandwidth: 110kHz; Input Bias Current: 3.5nA; Input Offset Voltage: 0.2mV; Max Supply Voltage: 5.5V; Min Supply Voltage: 3V; Number Of Channels: 1; Output Current Per Channel: 11mA; Response Time: 50us; Standoff Height: 0.36mm; TaMax_C: +125°C; TaMin_C: -40°C; TJmax_C: +150°C; Voltage Gain: 1V/V
U3 = CMP-0750075-1: 10-MHz, RRIO, CMOS Operational Amplifier for Cost-Sensitive Systems, DBV0005A (SOT-23-5); Alternate Manufacturer: Texas Instruments; SizeY_mm: 2.9; AEC Category: Q200; SizeAreaWB_mm2: 14.82; SizeZ_mm: 1.45; SizeX_mm: 2.8; CompType: IC; SizeArea_mm2: 8.12
U10 U11 = CMP-0094892-1: as U4 on sheet PMP41166D_Multi_Level_GaN_Card1
U12 = CMP-0126653-2: as U5 on sheet PMP41166D_Multi_Level_GaN_Card1
U13 U16 = CMP-0089765-2: as U6 on sheet PMP41166D_Multi_Level_GaN_Card1

## Sheet PMP41166D_Multi_Level_GaN_Card_Hardware.SchDoc
size 431 x 279 mm; Date: Not shown in title block; ApprovedBy: Not shown in title block; CheckedBy: Not shown in title block; Author: Not shown in title block; CompanyName: Not shown in title block; Engineer: Not shown in title block; Organization: Not shown in title block; Address1: Not shown in title block; Address2: Not shown in title block; Address3: Not shown in title block; Address4: Not shown in title block; DocumentNumber: 3; Revision: Use project parameter SCH_Rev; SheetNumber: 3; SheetTotal: 3; PageSetup: Record=PageOptions¦CenterHorizontal=True¦CenterVertical=True¦PrintScale=1.00¦XCorrection=1.00¦YCorrection=1.00¦PrintKind=0¦BorderSize=5000000¦LeftOffset=0¦BottomOffset=0¦Orientation=2¦PaperLength=1000¦PaperWidth=1000¦Scale=100¦PaperSource=15¦PrintQuality=600¦MediaType=1¦DitherType=10¦PaperKind=Letter¦PrintScaleMode=1
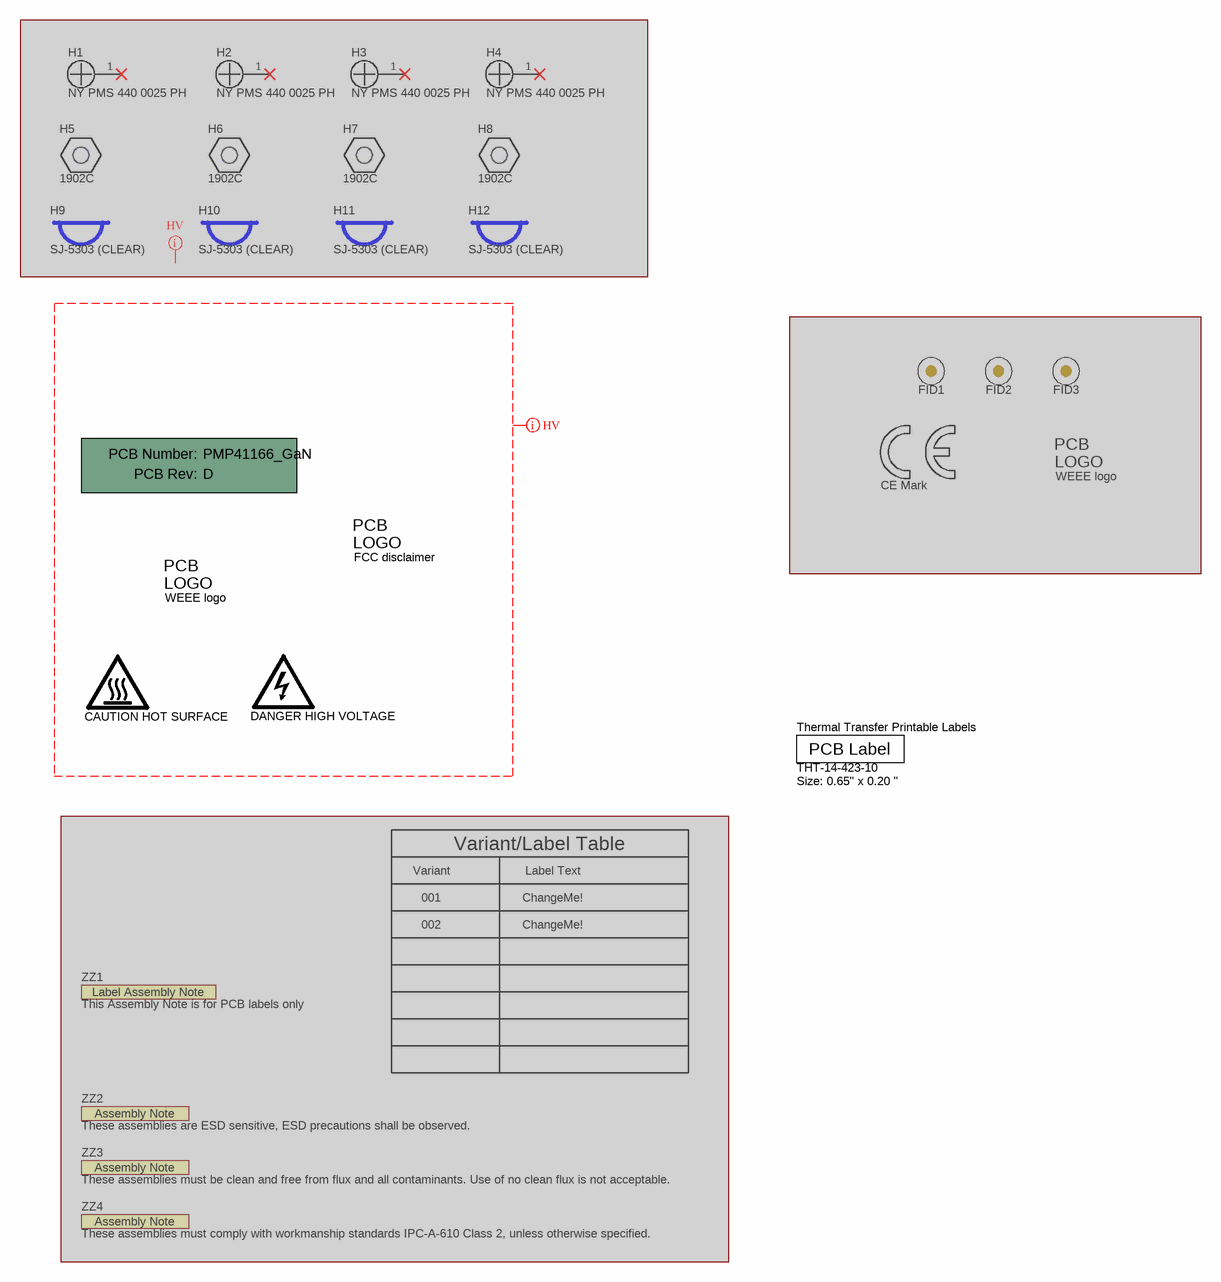
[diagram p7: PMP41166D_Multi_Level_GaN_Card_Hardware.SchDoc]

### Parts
!PCB  Printed Circuit Board  (value not drawn)  (mechanical)
FID1  Fiducial  [Fiducial10-20]  (value not drawn)  (masked out: inside a compile mask, not in the netlist)
FID2  Fiducial  [Fiducial10-20]  (value not drawn)  (masked out: inside a compile mask, not in the netlist)
FID3  Fiducial  [Fiducial10-20]  (value not drawn)  (masked out: inside a compile mask, not in the netlist)
H1  NY PMS 440 0025 PH  [NY PMS 440 0025 PH]  (masked out: inside a compile mask, not in the netlist)
H2  NY PMS 440 0025 PH  [NY PMS 440 0025 PH]  (masked out: inside a compile mask, not in the netlist)
H3  NY PMS 440 0025 PH  [NY PMS 440 0025 PH]  (masked out: inside a compile mask, not in the netlist)
H4  NY PMS 440 0025 PH  [NY PMS 440 0025 PH]  (masked out: inside a compile mask, not in the netlist)
H5  1902C  [Keystone_1902C]  (masked out: inside a compile mask, not in the netlist)
H6  1902C  [Keystone_1902C]  (masked out: inside a compile mask, not in the netlist)
H7  1902C  [Keystone_1902C]  (masked out: inside a compile mask, not in the netlist)
H8  1902C  [Keystone_1902C]  (masked out: inside a compile mask, not in the netlist)
H9  SJ-5303 (CLEAR)  [Bumpon_SJ5003Transparent]  (masked out: inside a compile mask, not in the netlist)
H10  SJ-5303 (CLEAR)  [Bumpon_SJ5003Transparent]  (masked out: inside a compile mask, not in the netlist)
H11  SJ-5303 (CLEAR)  [Bumpon_SJ5003Transparent]  (masked out: inside a compile mask, not in the netlist)
H12  SJ-5303 (CLEAR)  [Bumpon_SJ5003Transparent]  (masked out: inside a compile mask, not in the netlist)
Logo1  WEEE logo  [WEEE_Minimum]  (no BOM)
Logo2  CE Mark  [CE_Mark_5mm]  (no BOM)  (masked out: inside a compile mask, not in the netlist)
Logo3  FCC disclaimer  [FCC_disclaimer]  (no BOM)
Logo4  WEEE logo  [WEEE_Minimum]  (no BOM)  (masked out: inside a compile mask, not in the netlist)
LOGO5  CAUTION HOT SURFACE  [IEC_HotSurface_Small]  (no BOM)
LOGO6  DANGER HIGH VOLTAGE  [IEC_HighVoltage_Small]  (no BOM)
Thermal_Transfer_Printable_Labels  THT-14-423-10  Note: Size: 0.65" x 0.20 "  [Label_650x200]
ZZ1  This Assembly Note is for PCB labels only  [AssemblyNoteLabel]  (no BOM)  (masked out: inside a compile mask, not in the netlist)
ZZ2  These assemblies are ESD sensitive, ESD precautions shall be observed.  [AssemblyNote]  (no BOM)  (masked out: inside a compile mask, not in the netlist)
ZZ3  These assemblies must be clean and free from flux and all contaminants. Use of no clean flux is not acceptable.  [AssemblyNote]  (no BOM)  (masked out: inside a compile mask, not in the netlist)
ZZ4  These assemblies must comply with workmanship standards IPC-A-610 Class 2, unless otherwise specified.  [AssemblyNote]  (no BOM)  (masked out: inside a compile mask, not in the netlist)

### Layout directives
net class HV: (no net found under the mark)

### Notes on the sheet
- Variant
- Variant/Label Table
- Label Text
- 001
- 002
- ChangeMe!

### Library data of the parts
!PCB = CMP-0003618-2: Manufacturer: Any; PartNumber: PMP41166_GaN
FID1-FID3 = CMP-0077181-1: Fiducial mark.  There is nothing to buy or mount.
H1-H4 = CMP-0003617-1: Machine Screw, Round, #4-40 x 1/4, Nylon, Philips panhead; Manufacturer: B&F Fastener Supply; CompType: Hardware
H5-H8 = CMP-0003610-1: Standoff, Hex, 0.5"L #4-40 Nylon; Manufacturer: Keystone; CompType: Hardware
H9-H12 = CMP-0003620-1: Bumpon, Hemisphere, 0.44 X 0.20, Clear; Manufacturer: 3M
Logo1 Logo4 = CMP-0074769-1
Logo2 = CMP-0074844-1: SymbolCreator: a0412235
Logo3 = CMP-0074847-1: FCC_disclaimer; Library Reference: Logo
LOGO5 = CMP-0074837-1: IEC 61010-1 Hot Surface Warning; SymbolCreator: a0412235; Lib Reference: IEC_HotSurface
LOGO6 = CMP-0074835-1: IEC 61010-1 High Voltage Warning; SymbolCreator: a0412235; Lib Reference: IEC_HighVoltage
Thermal_Transfer_Printable_Labels = CMP-0003625-1: Thermal Transfer Printable Labels, 0.650" W x 0.200" H - 10,000 per roll; Manufacturer: Brady; CompType: Label
ZZ1 = CMP-0003616-3
ZZ2 = CMP-0077236-1
ZZ3 = CMP-0077237-1
ZZ4 = CMP-0077238-1

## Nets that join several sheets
PGND: PMP41166D_Multi_Level_GaN_Card1 (26 pins), PMP41166D_Multi_Level_GaN_Card2 (22 pins)
3V3: PMP41166D_Multi_Level_GaN_Card1 (J2.6), PMP41166D_Multi_Level_GaN_Card2 (5 pins)
5Vp: PMP41166D_Multi_Level_GaN_Card1 (11 pins), PMP41166D_Multi_Level_GaN_Card2 (8 pins)
12Vp: PMP41166D_Multi_Level_GaN_Card1 (9 pins), PMP41166D_Multi_Level_GaN_Card2 (5 pins)
HFFET_L2B: PMP41166D_Multi_Level_GaN_Card1 (J2.8), PMP41166D_Multi_Level_GaN_Card2 (R74.1)
HFFET_L3B: PMP41166D_Multi_Level_GaN_Card1 (J2.4), PMP41166D_Multi_Level_GaN_Card2 (R60.1)
SGND_H2A: PMP41166D_Multi_Level_GaN_Card1 (61 pins), PMP41166D_Multi_Level_GaN_Card2 (D3.2 R42.2)
SGND_H3A: PMP41166D_Multi_Level_GaN_Card1 (41 pins), PMP41166D_Multi_Level_GaN_Card2 (14 pins)
SGND_L2B: PMP41166D_Multi_Level_GaN_Card1 (8 pins), PMP41166D_Multi_Level_GaN_Card2 (32 pins)
SGND_L3B: PMP41166D_Multi_Level_GaN_Card1 (8 pins), PMP41166D_Multi_Level_GaN_Card2 (62 pins)
Vbulk1: PMP41166D_Multi_Level_GaN_Card1 (22 pins), PMP41166D_Multi_Level_GaN_Card2 (R30.2)
VFLY_SENSE: PMP41166D_Multi_Level_GaN_Card1 (J2.7), PMP41166D_Multi_Level_GaN_Card2 (C50.2 R1.1 U3.1)

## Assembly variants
001: not fitted FID1 FID2 FID3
